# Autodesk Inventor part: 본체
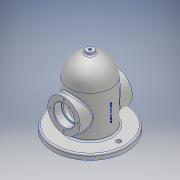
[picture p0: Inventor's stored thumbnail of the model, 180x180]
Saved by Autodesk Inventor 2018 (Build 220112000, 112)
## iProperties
Created: 2019-11
Part Number: 본체
Material: 알루미늄 6061
Document SubType Name: Modeling
Designer: CAD
Density: 2.7 g/cm^3
Appearance: 알루미늄 - 평지
Author: CAD
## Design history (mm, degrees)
sketch "스케치1"
  geometry: C1 r 70 at (0, 0); 1 further point
  constraints: 1 centre point, 1 coincident
  dimensions: "d0" = 140 diameter of C1
extrude "돌출1" new body sketch "스케치1" distance "d1" = 10; taper "d2" = 0 deg
sketch "스케치2"
  geometry: C1 r 40 at (0, 0); 1 further point
  constraints: 1 centre point, 1 coincident
  dimensions: "d3" = 80 diameter of C1
extrude "돌출2" join sketch "스케치2" distance "d4" = 80; taper "d5" = 0 deg
sketch "스케치3"
  geometry: L1 (0, 40)-(0, -40); C1 r 40 at (0, 0) reference; A1 r 40 centre (0, 0) between (0, 40) and (0, -40) reference; A2 r 40 centre (0, 0) between (0, -40) and (0, 40); 2 further points
  constraints: 4 point on circle, 2 coincident, 2 end point, 1 centre point, 1 midpoint, 1 vertical
revolve "회전1" sketch "스케치3" stored, may be unused: angle "d6" = 90 deg
node "작업 평면2"
  node "작업 평면1"
sketch "스케치4"
  geometry: 1 further point
sketch "스케치5"
  geometry: L1 (-70, 0)-(70, 0) reference; L2 (-70, 50)-(70, 50); L3 (0, 0)-(0, 161.96); C1 r 31 at (0, 50)
  constraints: 4 end point, 1 centre point, 1 midpoint, 1 parallel, 1 point on line, 1 vertical
  dimensions: "d9" = 50 distance between parallel lines of L1 L2; "d10" = 62 diameter of C1
extrude "돌출3" join sketch "스케치5" distance "d11" = 100; taper "d12" = 0 deg
node "작업 평면4"
sketch "스케치6"
  geometry: C1 r 7.5 at (0, 0); 1 further point
  constraints: 1 centre point, 1 coincident
  dimensions: "d15" = 15 diameter of C1
extrude "돌출4" join sketch "스케치6" distance "d16" = 15; taper "d17" = 0 deg
sketch "스케치7"
  geometry: 2 further points
  constraints: 1 coincident
hole "구멍1" sketch "스케치7" at (0, 0) diameter "d18" = 5.188; stored, may be unused: countersink angle "d22" = 90 deg, drill point angle "d24" = 118 deg; dims "d19" = 12, "d20" = 4, "d21" = 2, "d23" = 16
sketch "스케치8"
  geometry: C1 r 31 at (0, 0) reference; C2 r 16.5 at (0, 0); 1 further point
  constraints: 1 centre point, 1 coincident
  dimensions: "d25" = 33 diameter of C2
extrude "돌출5" cut sketch "스케치8" extent not by distance; stored distance "d26" = 15; taper "d27" = 0 deg
sketch "스케치9"
  geometry: C1 r 31 at (0, 0) reference; C2 r 20 at (0, 0); 1 further point
  constraints: 1 centre point, 1 coincident
  dimensions: "d28" = 40 diameter of C2
extrude "돌출6" cut sketch "스케치9" distance "d29" = 15; taper "d30" = 0 deg
sketch "스케치10"
  geometry: C1 r 2.594 at (0, 0) reference; C2 r 30 at (0, 0); 1 further point
  constraints: 1 centre point, 1 coincident
  dimensions: "d31" = 60 diameter of C2
extrude "돌출7" cut sketch "스케치10" distance "d32" = 90; taper "d33" = 0 deg
sketch "스케치11"
  geometry: L1 (0, 30)-(0, -30); C1 r 7.5 at (0, 0) reference; A1 r 30 centre (0, 0) between (0, -30) and (0, 30); A2 r 30 centre (0, 0) between (0, 30) and (0, -30) reference; 1 further point
  constraints: 3 point on circle, 2 end point, 1 centre point, 1 coincident
revolve "회전2" sketch "스케치11" stored, may be unused: angle "d34" = 90 deg
chamfer "모따기1" distance "d35" = 1; stored, may be unused: second distance "d36" = 2, angle "d37" = 45 deg
fillet "모깎기1" dims "d38" = 0.3
fillet "모깎기2" dims "d39" = 3
sketch "스케치12" dims "d41" = 52
  geometry: L1 (0, 0)-(0, 26); C1 r 16.5 at (0, 0) reference; C2 r 21 at (0, 0) reference; 3 further points
  constraints: 2 coincident, 2 end point, 1 vertical, 1 vertical alignment, 2 other
hole "구멍2" sketch "스케치12" at (0, 26) diameter "d42" = 3.242; stored, may be unused: countersink angle "d46" = 90 deg, drill point angle "d48" = 118 deg; dims "d43" = 8, "d44" = 4, "d45" = 2, "d47" = 10
sketch "스케치13"
  geometry: L1 (0, 0)-(-55, 0); C1 r 2.594 at (0, 0) reference; A1 r 55 centre (0, 0) between (-55, 0) and (55, 0); 3 further points
  constraints: 3 coincident, 2 end point, 2 point on circle, 1 centre point, 1 horizontal
  dimensions: "d52" = 110 diameter of A1
hole "구멍3" sketch "스케치13" at (-55, 0), (55, 0) diameter "d53" = 9; stored, may be unused: countersink angle "d57" = 90 deg, drill point angle "d59" = 118 deg; dims "d54" = 8, "d55" = 4, "d56" = 2, "d58" = 10
sketch "스케치14"
  geometry: 1 further point
node "작업 평면6"
sketch "스케치16"
  geometry: L1 (-70, 0)-(70, 0) reference; L2 (0, 0)-(0, 153.215); 1 further point
  constraints: 2 end point, 1 point on line, 1 vertical, 1 other
  dimensions: "d62" = 50 distance from line of L1 point (0, 50)
feature "엠보싱1" sketch "스케치16" dims "d63" = 0.5, "d64" = 0
node "솔리드1"
mirror "미러1"
pattern_circular "원형 패턴1" dims angle "d50" = 360 deg
mirror "미러2"
node "투영된 루프1"
node "투영된 루프2"
other parameters: "d14" = -135
